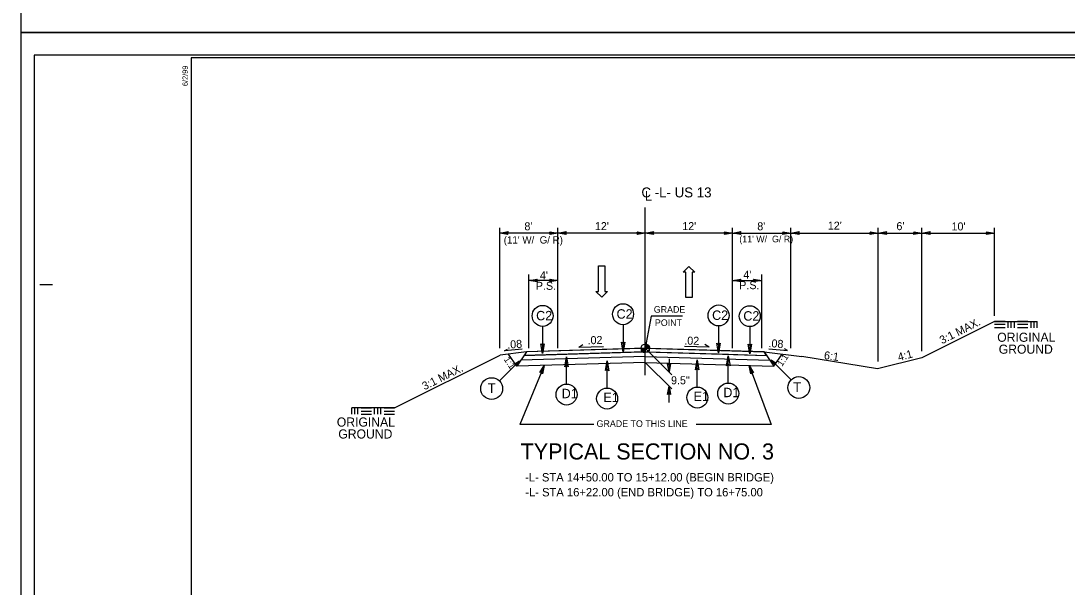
# Model space of a CAD drawing. Extents: x 9470 to 10081, y 10104 to 10463.
# Drawn here: x 9816.8 to 9960.6, y 10181.8 to 10259.6 of the extents above; entities that cross this region are included whole.
import ezdxf

# ---------------------------------------------------------------- set-up
doc = ezdxf.new("R2010")
doc.units = 0
for name, color, linetype in [('Old_Level_1', 7, 'Continuous'), ('Old_Level_11', 7, 'Continuous'), ('Old_Level_2', 7, 'Continuous'), ('Old_Level_21', 7, 'Continuous'), ('Old_Level_32', 7, 'Continuous'), ('Prop Lane Arrow CELL', 7, 'Continuous'), ('Prop Terminator CELL', 7, 'Continuous'), ('Sheet Cutting Line CELL', 7, 'Continuous'), ('Sheet Plot Border Inside CELL', 7, 'Continuous'), ('Sheet Plot Border Outside CELL', 7, 'Continuous'), ('Sheet Typical CELL', 7, 'Continuous'), ('Typical Hinge Slope Arterial CELL', 7, 'Continuous'), ('Typical ID Circle CELL', 7, 'Continuous'), ('Typical Pavement Slope CELL', 7, 'Continuous'), ('Typical Terminator CELL', 7, 'Continuous'), ('Typical Text ID Circle CELL', 7, 'Continuous')]:
    doc.layers.add(name, color=color, linetype=linetype)

msp = doc.modelspace()

# ---------------------------------------------------------------- linework, layer by layer
at = {"layer": 'Old_Level_1'}
for p, q in [((9902.63, 10210.87), (9902.63, 10233.91)), ((9882.63, 10214.58), (9882.63, 10231.11)), ((9890.63, 10214.58), (9890.63, 10231.11)), ((9914.63, 10214.58), (9914.63, 10231.11)), ((9922.63, 10214.58), (9922.63, 10231.11)), ((9934.63, 10212.74), (9934.63, 10231.11)), ((9940.63, 10214.2), (9940.63, 10231.11)), ((9950.63, 10219.04), (9950.63, 10231.11)), ((9890.63, 10230.41), (9882.63, 10230.41)), ((9902.63, 10230.41), (9890.63, 10230.41)), ((9914.63, 10230.41), (9902.63, 10230.41)), ((9914.63, 10230.41), (9922.63, 10230.41)), ((9922.63, 10230.41), (9934.63, 10230.41)), ((9934.63, 10230.41), (9940.63, 10230.41)), ((9940.63, 10230.41), (9950.63, 10230.41)), ((9886.63, 10214.58), (9886.63, 10224.72)), ((9890.63, 10223.89), (9886.63, 10223.89)), ((9914.63, 10223.89), (9918.63, 10223.89)), ((9918.63, 10214.58), (9918.63, 10224.72)), ((9950.63, 10218.26), (9956.5, 10218.26)), ((9952.06, 10218.26), (9950.63, 10218.26)), ((9952.49, 10217.41), (9952.49, 10218.26)), ((9952.92, 10217.41), (9952.92, 10218.26)), ((9953.35, 10217.41), (9953.35, 10218.26)), ((9955.21, 10218.26), (9953.78, 10218.26)), ((9955.64, 10217.41), (9955.64, 10218.26)), ((9956.07, 10217.41), (9956.07, 10218.26)), ((9956.5, 10217.41), (9956.5, 10218.26)), ((9952.06, 10217.83), (9950.63, 10217.83)), ((9952.06, 10217.41), (9950.63, 10217.41)), ((9955.21, 10217.83), (9953.78, 10217.83)), ((9955.21, 10217.41), (9953.78, 10217.41)), ((9902.63, 10214.58), (9902.63, 10215.16)), ((9886.31, 10214.09), (9882.68, 10213.65)), ((9902.63, 10214.09), (9885.98, 10213.59)), ((9902.63, 10214.58), (9886.31, 10214.09)), ((9902.05, 10214.58), (9902.63, 10214.58)), ((9903.22, 10214.58), (9902.63, 10214.58)), ((9902.63, 10213.99), (9902.63, 10214.58)), ((9902.63, 10214.58), (9902.63, 10213.99)), ((9902.63, 10214.58), (9906.27, 10210.94)), ((9902.63, 10214.58), (9918.96, 10214.09)), ((9918.96, 10214.09), (9924.16, 10213.47)), ((9888.74, 10212.21), (9885.38, 10204.1)), ((9902.63, 10212.63), (9906.27, 10208.99)), ((9905.89, 10213.11), (9905.89, 10211.32)), ((9916.91, 10212.2), (9919.94, 10204.1)), ((9905.89, 10207.14), (9905.89, 10209.37)), ((9868.16, 10206.39), (9862.29, 10206.39)), ((9862.29, 10205.53), (9862.29, 10206.39)), ((9862.72, 10205.53), (9862.72, 10206.39)), ((9863.15, 10205.53), (9863.15, 10206.39)), ((9863.58, 10206.39), (9865.01, 10206.39)), ((9863.58, 10205.96), (9865.01, 10205.96)), ((9863.58, 10205.53), (9865.01, 10205.53)), ((9865.44, 10205.53), (9865.44, 10206.39)), ((9865.87, 10205.53), (9865.87, 10206.39)), ((9866.3, 10205.53), (9866.3, 10206.39)), ((9866.73, 10206.39), (9868.16, 10206.39)), ((9866.73, 10205.96), (9868.16, 10205.96)), ((9866.73, 10205.53), (9868.16, 10205.53)), ((9895.54, 10204.1), (9885.38, 10204.1)), ((9919.94, 10204.1), (9909.62, 10204.1))]:
    msp.add_line(p, q, dxfattribs=at)
for points in [[(9902.64, 10215.16), (9902.64, 10215.16), (9902.64, 10214.58)], [(9902.65, 10215.16), (9902.65, 10214.58)], [(9902.66, 10215.16), (9902.66, 10214.58)], [(9902.67, 10215.16), (9902.67, 10214.58)], [(9902.69, 10215.16), (9902.69, 10214.58)], [(9902.7, 10215.16), (9902.7, 10214.58)], [(9902.71, 10215.16), (9902.71, 10214.58)], [(9902.72, 10215.16), (9902.72, 10214.58)], [(9902.73, 10215.16), (9902.73, 10214.58)], [(9902.74, 10215.15), (9902.74, 10214.58)], [(9902.76, 10215.15), (9902.76, 10214.58)], [(9902.77, 10215.15), (9902.77, 10214.58)], [(9902.78, 10215.15), (9902.78, 10214.58)], [(9902.79, 10215.14), (9902.79, 10214.58)], [(9902.8, 10215.14), (9902.8, 10214.58)], [(9902.82, 10215.14), (9902.82, 10214.58)], [(9902.83, 10215.13), (9902.83, 10214.58)], [(9902.84, 10215.13), (9902.84, 10214.58)], [(9902.85, 10215.12), (9902.85, 10214.58)], [(9902.86, 10215.12), (9902.86, 10214.58)], [(9902.87, 10215.11), (9902.87, 10214.58)], [(9902.89, 10215.11), (9902.89, 10214.58)], [(9902.9, 10215.1), (9902.9, 10214.58)], [(9902.91, 10215.1), (9902.91, 10214.58)], [(9902.92, 10215.09), (9902.92, 10214.58)], [(9902.93, 10215.08), (9902.93, 10214.58)], [(9902.94, 10215.08), (9902.94, 10214.58)], [(9902.96, 10215.07), (9902.96, 10214.58)], [(9902.97, 10215.06), (9902.97, 10214.58)], [(9902.98, 10215.05), (9902.98, 10214.58)], [(9902.99, 10215.04), (9902.99, 10214.58)], [(9903, 10215.03), (9903, 10214.58)], [(9903.01, 10215.02), (9903.01, 10214.58)], [(9902.05, 10214.58), (9902.05, 10214.52)], [(9902.06, 10214.58), (9902.06, 10214.45)], [(9902.08, 10214.58), (9902.08, 10214.4)], [(9902.09, 10214.58), (9902.09, 10214.37)], [(9902.1, 10214.58), (9902.1, 10214.34)], [(9902.11, 10214.58), (9902.11, 10214.32)], [(9902.12, 10214.58), (9902.12, 10214.3)], [(9902.13, 10214.58), (9902.13, 10214.27)], [(9902.15, 10214.58), (9902.15, 10214.26)], [(9902.16, 10214.58), (9902.16, 10214.24)], [(9902.17, 10214.58), (9902.17, 10214.22)], [(9902.18, 10214.58), (9902.18, 10214.21)], [(9902.19, 10214.58), (9902.19, 10214.2)], [(9902.2, 10214.58), (9902.2, 10214.18)], [(9902.22, 10214.58), (9902.22, 10214.17)], [(9902.23, 10214.58), (9902.23, 10214.16)], [(9902.24, 10214.58), (9902.24, 10214.15)], [(9902.25, 10214.58), (9902.25, 10214.14)], [(9902.26, 10214.58), (9902.26, 10214.13)], [(9902.27, 10214.58), (9902.27, 10214.12)], [(9902.29, 10214.58), (9902.29, 10214.11)], [(9902.3, 10214.58), (9902.3, 10214.1)], [(9902.31, 10214.58), (9902.31, 10214.09)], [(9902.32, 10214.58), (9902.32, 10214.09)], [(9902.33, 10214.58), (9902.33, 10214.08)], [(9902.34, 10214.58), (9902.34, 10214.07)], [(9902.36, 10214.58), (9902.36, 10214.06)], [(9902.37, 10214.58), (9902.37, 10214.06)], [(9902.38, 10214.58), (9902.38, 10214.05)], [(9902.39, 10214.58), (9902.39, 10214.05)], [(9902.4, 10214.58), (9902.4, 10214.04)], [(9902.41, 10214.58), (9902.41, 10214.04)], [(9902.43, 10214.58), (9902.43, 10214.03)], [(9902.44, 10214.58), (9902.44, 10214.03)], [(9902.45, 10214.58), (9902.45, 10214.02)], [(9902.46, 10214.58), (9902.46, 10214.02)], [(9902.47, 10214.58), (9902.47, 10214.02)], [(9902.48, 10214.58), (9902.48, 10214.01)], [(9902.5, 10214.58), (9902.5, 10214.01)], [(9902.51, 10214.58), (9902.51, 10214.01)], [(9902.52, 10214.58), (9902.52, 10214.01)], [(9902.53, 10214.58), (9902.53, 10214)], [(9902.54, 10214.58), (9902.54, 10214)], [(9902.56, 10214.58), (9902.56, 10214)], [(9902.57, 10214.58), (9902.57, 10214)], [(9902.58, 10214.58), (9902.58, 10214)], [(9902.59, 10214.58), (9902.59, 10214)], [(9902.6, 10214.58), (9902.6, 10214)], [(9902.61, 10214.58), (9902.61, 10213.99)], [(9902.63, 10214.58), (9902.63, 10213.99), (9902.63, 10213.99)], [(9903.03, 10215.01), (9903.03, 10214.58)], [(9903.04, 10215), (9903.04, 10214.58)], [(9903.05, 10214.99), (9903.05, 10214.58)], [(9903.06, 10214.98), (9903.06, 10214.58)], [(9903.07, 10214.97), (9903.07, 10214.58)], [(9903.08, 10214.95), (9903.08, 10214.58)], [(9903.1, 10214.94), (9903.1, 10214.58)], [(9903.11, 10214.92), (9903.11, 10214.58)], [(9903.12, 10214.91), (9903.12, 10214.58)], [(9903.13, 10214.89), (9903.13, 10214.58)], [(9903.14, 10214.87), (9903.14, 10214.58)], [(9903.15, 10214.85), (9903.15, 10214.58)], [(9903.17, 10214.82), (9903.17, 10214.58)], [(9903.18, 10214.79), (9903.18, 10214.58)], [(9903.19, 10214.76), (9903.19, 10214.58)], [(9903.2, 10214.72), (9903.2, 10214.58)], [(9903.21, 10214.66), (9903.21, 10214.58)]]:
    msp.add_lwpolyline(points, dxfattribs=at)
msp.add_circle((9902.63, 10214.58), 0.585, dxfattribs=at)
for start, end in [(359.9905, 89.9905), (179.9905, 269.9905)]:
    msp.add_arc((9902.63, 10214.58), 0.585, start, end, dxfattribs=at)
at = {"layer": 'Old_Level_11'}
for p, q in [((9903.44, 10219.01), (9902.63, 10214.58)), ((9907.74, 10219.01), (9903.44, 10219.01)), ((9883.27, 10214.24), (9883.7, 10214.45)), ((9885.72, 10214.44), (9883.27, 10214.24)), ((9919.61, 10214.5), (9922.19, 10214.28)), ((9922.19, 10214.28), (9921.76, 10214.5))]:
    msp.add_line(p, q, dxfattribs=at)
at = {"layer": 'Old_Level_2'}
for p, q in [((9893.51, 10214.74), (9894.07, 10215.08)), ((9911.39, 10214.74), (9910.83, 10215.08)), ((9893.51, 10214.74), (9896.88, 10214.81)), ((9911.39, 10214.74), (9908.02, 10214.81))]:
    msp.add_line(p, q, dxfattribs=at)
at = {"layer": 'Old_Level_21'}
for p, q in [((9886.31, 10214.09), (9885.98, 10213.59)), ((9885.98, 10213.59), (9902.15, 10214.08)), ((9902.05, 10214.56), (9886.31, 10214.09)), ((9902.15, 10214.08), (9902.32, 10214.08)), ((9902.94, 10214.08), (9903.11, 10214.08)), ((9918.96, 10214.09), (9903.22, 10214.56)), ((9919.29, 10213.59), (9918.96, 10214.09))]:
    msp.add_line(p, q, dxfattribs=at)
for points in [[(9902.05, 10214.52), (9902.05, 10214.52)], [(9903.11, 10214.08), (9914.08, 10213.75), (9919.29, 10213.59)], [(9903.22, 10214.56), (9903.22, 10214.56)]]:
    msp.add_lwpolyline(points, dxfattribs=at)
for start, end in [(186.1998, 200.9216), (186.1968, 186.1998), (200.9216, 206.5155), (206.5155, 213.4322), (213.4322, 220.9889), (220.9889, 222.7056), (222.7056, 224.4209), (224.4209, 229.1147), (229.1147, 230.6498), (230.6498, 232.1035), (232.1035, 236.316), (236.316, 237.6963), (237.6963, 238.027), (301.987, 358.3421)]:
    msp.add_arc((9902.63, 10214.58), 0.585, start, end, dxfattribs=at)
for start_param, end_param in [(4.731444, 4.820595), (4.784188, 4.820595), (4.820595, 4.940236), (4.820595, 4.940236), (4.940236, 5.077539), (4.940236, 5.077539), (5.077539, 5.128372), (5.077539, 5.128372), (5.128372, 5.175172), (5.128372, 5.175172), (5.175172, 5.258853), (5.175172, 5.258853), (5.258853, 5.29589), (5.258853, 5.29589), (5.29589, 5.32015), (5.29589, 5.32015), (0.963144, 1.551832), (0.963144, 1.551832)]:
    msp.add_ellipse((9902.63, 10214.58), major_axis=(0, -0.878), ratio=0.666667, start_param=start_param, end_param=end_param, dxfattribs=at)
at = {"layer": 'Prop Lane Arrow CELL'}
for p, q in [((9896.22, 10222.39), (9896.22, 10225.89)), ((9896.22, 10225.89), (9897.05, 10225.89)), ((9897.05, 10225.89), (9897.05, 10222.39)), ((9907.85, 10225.05), (9908.62, 10225.83)), ((9908.62, 10225.83), (9909.42, 10225.05)), ((9908.22, 10225.05), (9907.85, 10225.05)), ((9908.22, 10221.55), (9908.22, 10225.05)), ((9909.42, 10225.05), (9909.05, 10225.05)), ((9909.05, 10225.05), (9909.05, 10221.55)), ((9896.65, 10221.6), (9895.85, 10222.39)), ((9895.85, 10222.39), (9896.22, 10222.39)), ((9897.42, 10222.39), (9896.65, 10221.6)), ((9897.05, 10222.39), (9897.42, 10222.39)), ((9909.05, 10221.55), (9908.22, 10221.55))]:
    msp.add_line(p, q, dxfattribs=at)
at = {"layer": 'Prop Terminator CELL'}
for points in [[(9883.76, 10230.22), (9882.63, 10230.41), (9883.77, 10230.61), (9883.62, 10230.41)], [(9889.51, 10230.6), (9890.63, 10230.41), (9889.5, 10230.21), (9889.65, 10230.41)], [(9891.76, 10230.22), (9890.63, 10230.41), (9891.77, 10230.61), (9891.62, 10230.41)], [(9901.51, 10230.6), (9902.63, 10230.41), (9901.5, 10230.21), (9901.65, 10230.41)], [(9903.76, 10230.22), (9902.63, 10230.41), (9903.77, 10230.61), (9903.62, 10230.41)], [(9913.51, 10230.6), (9914.63, 10230.41), (9913.5, 10230.21), (9913.65, 10230.41)], [(9915.76, 10230.22), (9914.63, 10230.41), (9915.77, 10230.61), (9915.62, 10230.41)], [(9921.51, 10230.6), (9922.63, 10230.41), (9921.5, 10230.21), (9921.65, 10230.41)], [(9923.76, 10230.22), (9922.63, 10230.41), (9923.77, 10230.61), (9923.62, 10230.41)], [(9933.51, 10230.6), (9934.63, 10230.41), (9933.5, 10230.21), (9933.65, 10230.41)], [(9935.76, 10230.22), (9934.63, 10230.41), (9935.77, 10230.61), (9935.62, 10230.41)], [(9935.76, 10230.22), (9934.63, 10230.41), (9935.77, 10230.61), (9935.62, 10230.41)], [(9939.51, 10230.6), (9940.63, 10230.41), (9939.5, 10230.21), (9939.65, 10230.41)], [(9939.51, 10230.6), (9940.63, 10230.41), (9939.5, 10230.21), (9939.65, 10230.41)], [(9941.76, 10230.22), (9940.63, 10230.41), (9941.77, 10230.61), (9941.62, 10230.41)], [(9941.76, 10230.22), (9940.63, 10230.41), (9941.77, 10230.61), (9941.62, 10230.41)], [(9949.51, 10230.6), (9950.63, 10230.41), (9949.5, 10230.21), (9949.65, 10230.41)], [(9887.76, 10223.7), (9886.63, 10223.89), (9887.77, 10224.09), (9887.62, 10223.89)], [(9889.51, 10224.08), (9890.63, 10223.89), (9889.5, 10223.69), (9889.65, 10223.89)], [(9915.76, 10223.7), (9914.63, 10223.89), (9915.77, 10224.09), (9915.62, 10223.89)], [(9917.51, 10224.08), (9918.63, 10223.89), (9917.5, 10223.69), (9917.65, 10223.89)], [(9888.13, 10211.25), (9888.74, 10212.21), (9888.49, 10211.09), (9888.36, 10211.3)], [(9906.09, 10212.44), (9905.89, 10211.32), (9905.69, 10212.45), (9905.89, 10212.31)], [(9917.12, 10211.08), (9916.91, 10212.2), (9917.49, 10211.21), (9917.25, 10211.28)], [(9905.7, 10208.25), (9905.89, 10209.37), (9906.09, 10208.24), (9905.89, 10208.38)]]:
    msp.add_lwpolyline(points, close=True, dxfattribs=at)
at = {"layer": 'Sheet Cutting Line CELL'}
for p, q in [((9816.84, 10411.98), (9816.84, 10257.98)), ((9816.84, 10257.98), (10052.6, 10257.98)), ((10052.6, 10257.98), (9816.84, 10257.98)), ((9816.84, 10257.98), (9816.84, 10103.98))]:
    msp.add_line(p, q, dxfattribs=at)
at = {"layer": 'Sheet Plot Border Inside CELL'}
msp.add_lwpolyline([(10051.97, 10254.84), (9818.66, 10254.84), (9818.66, 10107.13), (10051.97, 10107.13)], close=True, dxfattribs=at)
at = {"layer": 'Sheet Plot Border Outside CELL'}
for points in [[(10052.6, 10411.98), (9816.84, 10411.98), (9816.84, 10257.98), (10052.6, 10257.98)], [(10052.6, 10257.98), (9816.84, 10257.98), (9816.84, 10103.98), (10052.6, 10103.98)]]:
    msp.add_lwpolyline(points, close=True, dxfattribs=at)
at = {"layer": 'Sheet Typical CELL'}
msp.add_line((9819.43, 10223.33), (9821.18, 10223.33), dxfattribs=at)
msp.add_lwpolyline([(10050.22, 10254.48), (9840.22, 10254.48), (9840.22, 10107.48), (10050.22, 10107.48)], close=True, dxfattribs=at)
at = {"layer": 'Typical Hinge Slope Arterial CELL'}
for p, q in [((9950.63, 10218.26), (9940.63, 10213.26)), ((9868.16, 10206.39), (9882.68, 10213.65)), ((9934.53, 10211.74), (9924.16, 10213.47)), ((9940.63, 10213.26), (9934.53, 10211.74))]:
    msp.add_line(p, q, dxfattribs=at)
at = {"layer": 'Typical ID Circle CELL'}
for p, q in [((9888.52, 10217.59), (9888.52, 10213.86)), ((9899.57, 10217.82), (9899.57, 10214.09)), ((9912.7, 10217.65), (9912.7, 10213.92)), ((9916.99, 10217.55), (9916.99, 10213.82)), ((9882.58, 10210.11), (9885.33, 10212.85)), ((9891.81, 10209.66), (9891.81, 10213.39)), ((9897.38, 10209.12), (9897.38, 10212.84)), ((9909.78, 10209.25), (9909.78, 10212.98)), ((9914.03, 10209.8), (9914.03, 10213.53)), ((9922.66, 10210.24), (9919.92, 10212.99))]:
    msp.add_line(p, q, dxfattribs=at)
for centre, radius in [((9888.52, 10219.03), 1.44), ((9899.57, 10219.26), 1.44), ((9912.7, 10219.09), 1.44), ((9916.99, 10218.99), 1.44), ((9881.52, 10209.04), 1.5), ((9891.81, 10208.22), 1.44), ((9914.03, 10208.36), 1.44), ((9923.72, 10209.18), 1.5), ((9897.38, 10207.67), 1.44), ((9909.78, 10207.81), 1.44)]:
    msp.add_circle(centre, radius, dxfattribs=at)
at = {"layer": 'Typical Pavement Slope CELL'}
for p, q in [((9884.98, 10212.1), (9883.85, 10213.79)), ((9886.31, 10214.09), (9884.98, 10212.1)), ((9902.63, 10214.09), (9919.29, 10213.59)), ((9918.96, 10214.09), (9920.29, 10212.1)), ((9920.29, 10212.1), (9921.42, 10213.79)), ((9902.63, 10212.63), (9884.98, 10212.1)), ((9902.63, 10213.44), (9885.53, 10212.93)), ((9902.63, 10213.44), (9919.73, 10212.93)), ((9902.63, 10212.63), (9920.29, 10212.1))]:
    msp.add_line(p, q, dxfattribs=at)
at = {"layer": 'Typical Terminator CELL'}
for points in [[(9888.75, 10215.2), (9888.52, 10213.86), (9888.28, 10215.21), (9888.52, 10215.04)], [(9899.8, 10215.43), (9899.57, 10214.09), (9899.34, 10215.44), (9899.57, 10215.27)], [(9912.94, 10215.26), (9912.7, 10213.92), (9912.47, 10215.26), (9912.7, 10215.09)], [(9917.22, 10215.16), (9916.99, 10213.82), (9916.76, 10215.16), (9916.99, 10214.99)], [(9884.72, 10212.42), (9885.33, 10212.85), (9884.9, 10212.24), (9884.87, 10212.4)], [(9891.58, 10212.05), (9891.81, 10213.39), (9892.05, 10212.04), (9891.81, 10212.22)], [(9897.15, 10211.51), (9897.38, 10212.84), (9897.61, 10211.5), (9897.38, 10211.67)], [(9909.55, 10211.64), (9909.78, 10212.98), (9910.01, 10211.64), (9909.78, 10211.81)], [(9913.8, 10212.19), (9914.03, 10213.53), (9914.27, 10212.19), (9914.03, 10212.36)], [(9920.34, 10212.38), (9919.92, 10212.99), (9920.53, 10212.56), (9920.37, 10212.53)]]:
    msp.add_lwpolyline(points, close=True, dxfattribs=at)

# ---------------------------------------------------------------- texts
at = {"layer": 'Old_Level_1'}
msp.add_text('C -L- US 13', height=1.3647, dxfattribs=at).set_placement((9902.1, 10235.31))
msp.add_text('L', height=1.37, rotation=359.9469, dxfattribs=at).set_placement((9902.56, 10234.84))
at = {"layer": 'Old_Level_11'}
for s, height, p in [("8'", 1.1, (9886.02, 10230.79)), ("12'", 1.1, (9895.71, 10230.81)), ("12'", 1.1, (9907.71, 10230.81)), ("8'", 1.1, (9918.02, 10230.79)), ("12'", 1.1, (9927.71, 10230.88)), ("6'", 1.1, (9937.14, 10230.81)), ("10'", 1.1, (9944.71, 10230.77)), ("(11' W/  G/ R)", 1, (9883.18, 10228.97)), ("(11' W/  G/ R)", 0.91, (9915.55, 10229.14)), ("4'", 1.1, (9888.15, 10224.05)), ("4'", 1.1, (9916.1, 10224.14)), ('P.S.', 1.1, (9887.59, 10222.61)), ('P.S.', 1.1, (9915.54, 10222.7)), ('GRADE', 0.91, (9903.8, 10219.46)), ('POINT', 0.91, (9903.95, 10217.64)), ('9.5"', 1.1, (9906.17, 10209.63)), ('GRADE TO THIS LINE ', 0.91, (9895.94, 10203.77))]:
    msp.add_text(s, height=height, dxfattribs=at).set_placement(p)
for s, height, rotation, p in [('3:1 MAX.', 1.1, 26.7764, (9943.41, 10215.12)), ('ORIGINAL', 1.25, 0.0013, (9950.99, 10215.47)), ('.08 ', 1.1, 4.0383, (9883.7, 10214.52)), ('.02', 1.1, 1.1939, (9894.71, 10215.13)), ('.02', 1.1, 358.8061, (9907.98, 10215.09)), ('.08 ', 1.1, 355.9617, (9919.53, 10214.75)), ('GROUND', 1.25, 0.0013, (9951.2, 10213.83)), ('1:1', 0.91, 56.3099, (9921.42, 10212.01)), ('6:1', 1.1, 351.993, (9927.13, 10213.11)), ('4:1', 1.1, 14.9339, (9937.48, 10212.81)), ('3:1 MAX.', 1.1, 26.3459, (9872.29, 10208.8)), ('1:1', 0.91, 303.6901, (9883.15, 10213.05)), ('ORIGINAL', 1.25, 359.9987, (9860.24, 10203.82)), ('GROUND', 1.25, 359.9987, (9860.45, 10202.18))]:
    msp.add_text(s, height=height, rotation=rotation, dxfattribs=at).set_placement(p)
at = {"layer": 'Old_Level_32'}
for s, height, p in [('TYPICAL SECTION NO. 3', 2.21, (9885.5, 10199.3)), ('-L- STA 14+50.00 TO 15+12.00 (BEGIN BRIDGE)', 1.15, (9886.12, 10196.28)), ('-L- STA 16+22.00 (END BRIDGE) TO 16+75.00', 1.15, (9886.14, 10194.23))]:
    msp.add_text(s, height=height, dxfattribs=at).set_placement(p)
at = {"layer": 'Sheet Typical CELL'}
msp.add_text('6/2/99', height=0.735, rotation=90, dxfattribs=at).set_placement((9839.77, 10250.6))
at = {"layer": 'Typical Text ID Circle CELL'}
for s, height, p in [('C2', 1.291, (9887.63, 10218.42)), ('C2', 1.291, (9898.68, 10218.65)), ('C2', 1.291, (9911.81, 10218.48)), ('C2', 1.291, (9916.1, 10218.38)), ('T ', 1.345, (9880.96, 10208.42)), ('T ', 1.345, (9922.95, 10208.56)), ('D1', 1.291, (9891.14, 10207.72)), ('E1', 1.291, (9896.87, 10207.18)), ('E1', 1.291, (9909.27, 10207.32)), ('D1', 1.291, (9913.35, 10207.86))]:
    msp.add_text(s, height=height, dxfattribs=at).set_placement(p)

doc.saveas('drawing.dxf')
